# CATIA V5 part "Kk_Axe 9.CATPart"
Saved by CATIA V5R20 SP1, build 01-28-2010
Part number: Axe 9
Bounding box of the stored display mesh (mm): x -39 to 39, y -390 to 390, z -50 to 38.994
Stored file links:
  G:\Khaled_CFAO_2011\SIL\SIL_GR1\gperrin\Khaled\CAD_CATIA\Khaled\Kk_Axe 9.CATPart
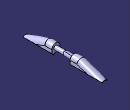
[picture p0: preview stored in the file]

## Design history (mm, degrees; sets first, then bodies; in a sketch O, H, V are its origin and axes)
Set1
  Plane1: type Offset, RefPlane zx-plane, Offset 200
  Plane2: type Angle, RefPlane Plane1, Direction edge [face of Pad1 from Sketch2.L1 | end face of Pad1], Angle 10
  Plane3: type Offset, RefPlane Plane1, Offset 150
  Line1: type PtPt, FirstPoint vertex [face of Pad1 from Sketch2.L1 | face of Pad1 from Sketch2.A2 | end face of Pad1], SecondPoint vertex [end face of Pad1 | face of Pad1 from Sketch2.A2 | face of Pad1 from Sketch2.L6]
  Plane4: type Angle, RefPlane end face of Pad1, Direction Line1, Angle -19
  Plane5: type Offset, RefPlane zx-plane, Offset 30
  Plane6: type Offset, RefPlane zx-plane, Offset 30, reversed
Body1 (main body)
  Sketch1 on yz-plane, origin (0, 0, 0), H (0, 1, 0), V (0, 0, 1)
    line L1 (0, 0) -> (90, 0)
    line L2 (90, 0) -> (90, 19)
    line L3 (90, 19) -> (0, 19)
    line L4 (0, 19) -> (0, 0)
    axis line L5 (-37, 0) -> (124, 0)
    point P4 (-37, 0)
    length L3 = 90
    length L2 = 19
    horizontal: L1 H, L3 H, L5 H
    vertical: L2 V, L4 V
    coincidence: P4 H
  Shaft1: profile Sketch1, axis Sketch1.L5, angle 360
  Sketch2 on face of Shaft1 from Sketch1.L2, origin (0, 90, 0), H (-1, 0, 0), V (0, 0, 1)
    arc A1 centre (0, 0) radius 39 from (39, 0) to (-39, 0) ccw
    line L1 (22.939, -50) -> (20.7123, -50)
    line L2 (-39, 0) -> (-39, -33.8087)
    point P1 (-39, 0)
    point P2 (-39, -50)
    line L3 (39, 0) -> (39, -33.939)
    line L4 (39, -33.939) -> (22.939, -50)
    line L5 (-39, -33.8087) -> (-22.8087, -50)
    arc A2 centre (0, -64) radius 25 from (20.7123, -50) to (-20.7123, -50) ccw
    point P8 (0, -64)
    line L6 (-20.7123, -50) -> (-22.8087, -50)
    radius A1 = 39
    radius A1 = 39 (reference)
    angle L3 L4 = 45
    length L4 = 22.7137
    distance P1 P2 = 50
    angle L2 L5 = 45
    length L5 = 22.898
    radius A2 = 25
    horizontal: L1 H, L6 H
    tangency: L2 A1, L3 A1, A2 A1
    coincidence: L2 P2, L1 P2, P8 V, L1 L6
  Pad1: profile Sketch2, direction (0, 1, 0), length 300
  Sketch3 on Plane4, origin (0, 364.0536, -125.3537), H (1, 0, 0), V (0, 0.3256, 0.9455)
    arc A1 centre (0, 50.6957) radius 39 from (39, 50.6957) to (-39, 50.6957) ccw
    point P1 (0, 50.6957)
    reference projected line E1 (-20.7123, 79.6957) -> (20.7123, 79.6957) from Line1
    line L1 (-69, 50.6957) -> (-39, 50.6957)
    line L2 (78, 50.6957) -> (78, 179)
    line L3 (78, 179) -> (-69, 179)
    line L4 (-69, 179) -> (-69, 50.6957)
    point P7 (39, 50.6957)
    line L5 (39, 50.6957) -> (78, 50.6957)
    radius A1 = 39
    distance P1 E1 = 29
    coincidence: P1 V, L1 P7, L1 L5
    horizontal: L1 H, L3 H, L5 H
    vertical: L2 V, L4 V
  Pocket1: profile Sketch3, direction (0, 0.9455, -0.3256), through (limit type 3)
  Mirror1: of Shaft1, Sketch1, Pad1, Sketch2, Pocket1, Sketch3, about zx-plane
